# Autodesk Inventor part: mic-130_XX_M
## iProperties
Shininess: 20.0
Length Units: 11269
Angle Units: 11279
Time Units: 11290
Mass Units: 11283
Length Display Precision: 2
Angle Display Precision: 2
Part Number: mic-130_XX_M
Material: Nichtrostender Stahl - 440C
Document SubType Name: Modellieren
Description: mic 130 Sensoren
Checked By: Alves
Created: 2005-08
Designer: Ohle
Manufacturer: Standard
Standards Organization: Custom
Density: 0.0
Volumn: 0.0
Area: 0.0
PropertySet Name: Model Information
Control State: 0
Master: False
Checked Out: False
Last Check In By: Kramp
Last Check In Date: 2005-08-09
BESTELLNUMMER: mic-130/XX/M
ME: ST
Title: mic Sensoren
Author: Ohle
Comments: keine Bemerkung
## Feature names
1. Grundkörper [Revolution]
2. Bohrung1 [Hole]
3. Pole [Extrusion]
4. Abrundung Pole [Fillet]
5. Verdrehsicherung [Extrusion]
